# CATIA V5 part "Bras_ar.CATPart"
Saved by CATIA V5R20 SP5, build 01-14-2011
Part number: Skl_Bras_ar
Publications: "Plan xy", "Axe_glissiere_bras_ar/vol_ar", "Axe_pivot_vol_ar/pignon_ar"
Bounding box of the stored display mesh (mm): x 0 to 0, y 142.727 to 182.727, z 0 to 150
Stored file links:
  U:\2A\CFAO\dossier sans titre\Bras_ar.CATPart
  U:\2A\CFAO\dossier sans titre\Skl_gouvernail.CATProduct
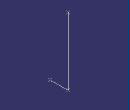
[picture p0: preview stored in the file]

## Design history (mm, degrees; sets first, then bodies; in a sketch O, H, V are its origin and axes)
Set1
  Point1 to Point3: linked copy from another document
Body1 (main body)
  Line1 "Axe_glissiere_bras_ar/vol_ar": type PtPt, FirstPoint Point1, SecondPoint Point2
  Line2 "Axe_pivot_vol_ar/pignon_ar": type PtPt, FirstPoint Point3, SecondPoint Point2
